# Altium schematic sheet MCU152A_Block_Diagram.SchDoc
size 431 x 279 mm; Date: Not shown in title block; ApprovedBy: Not shown in title block; CheckedBy: Not shown in title block; Author: Not shown in title block; CompanyName: Not shown in title block; Engineer: Not shown in title block; Organization: Not shown in title block; Address1: Not shown in title block; Address2: Not shown in title block; Address3: Not shown in title block; Address4: Not shown in title block; DocumentNumber: 1; Revision: Use project parameter SCH_Rev; SheetNumber: 1; SheetTotal: 8; PageSetup: Record=PageOptions¦CenterHorizontal=True¦CenterVertical=True¦PrintScale=1.00¦XCorrection=1.00¦YCorrection=1.00¦PrintKind=0¦BorderSize=5000000¦LeftOffset=0¦BottomOffset=0¦Orientation=2¦PaperLength=1000¦PaperWidth=1000¦Scale=100¦PaperSource=15¦PrintQuality=600¦MediaType=1¦DitherType=10¦PaperKind=Letter¦PrintScaleMode=1
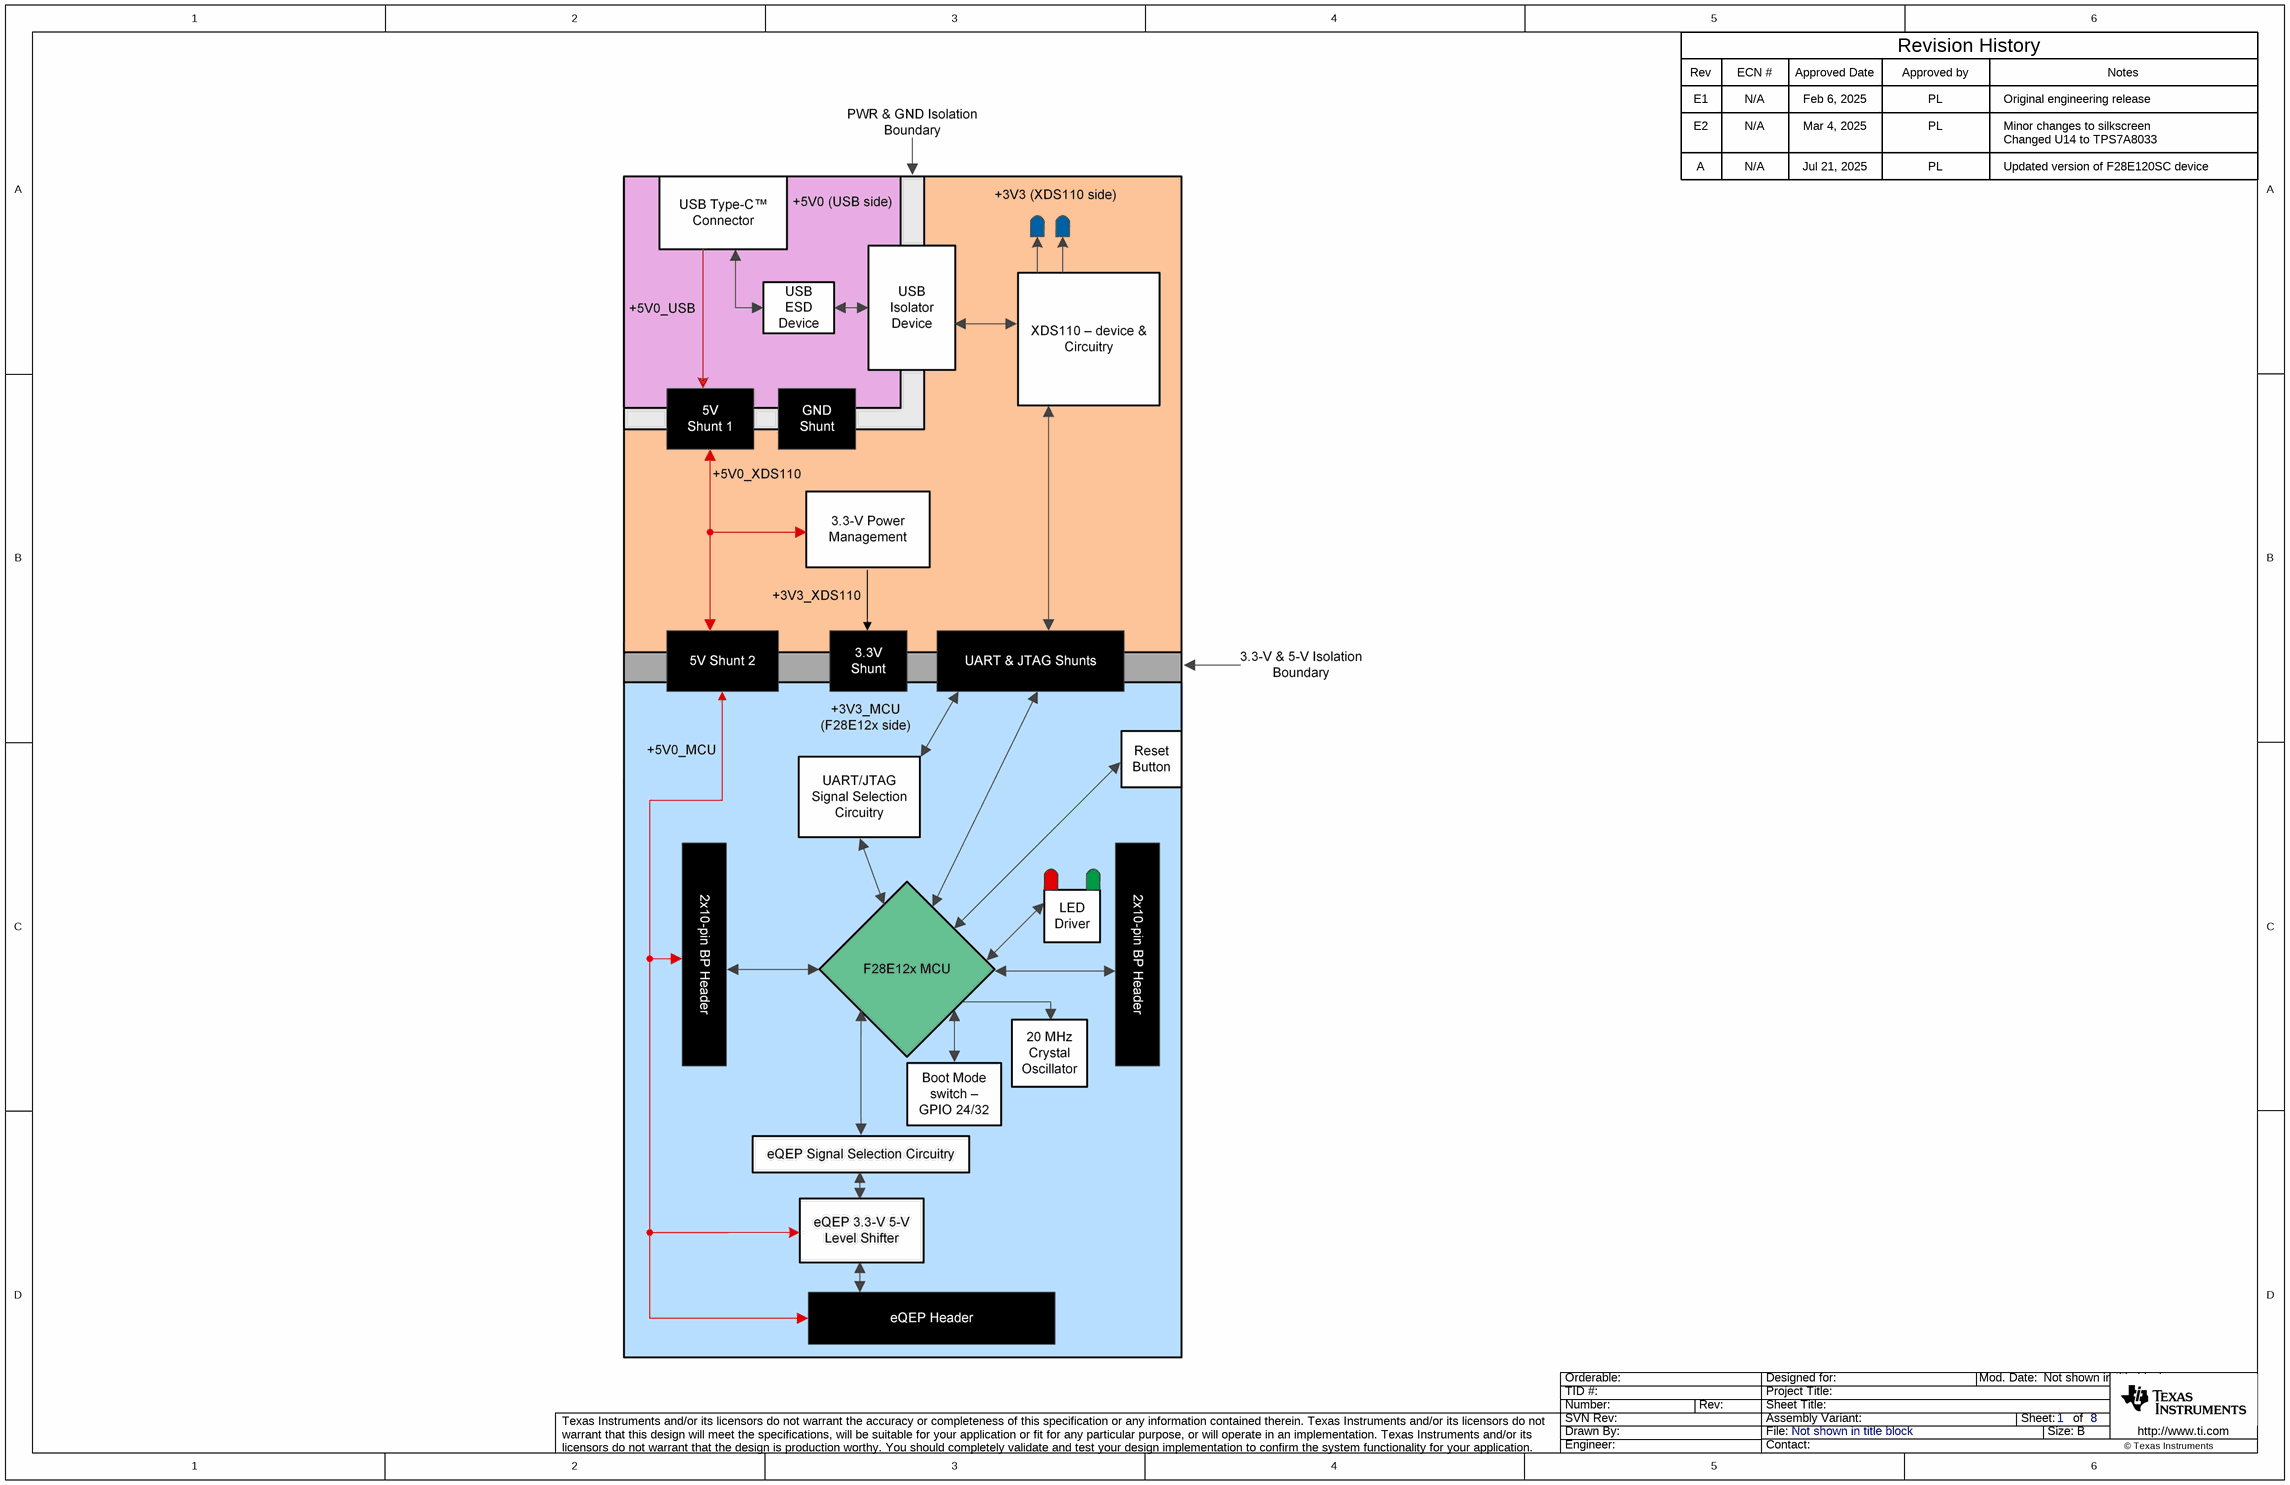
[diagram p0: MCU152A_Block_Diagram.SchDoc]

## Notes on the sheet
- Rev
- E1
- ECN #
- N/A
- Approved Date
- Feb 6, 2025
- Approved by
- PL
- Revision History
- Original engineering release
- Notes
- E2
- A
- Mar 4, 2025
- Jul 21, 2025
- Minor changes to silkscreen
- Changed U14 to TPS7A8033
- Updated version of F28E120SC device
